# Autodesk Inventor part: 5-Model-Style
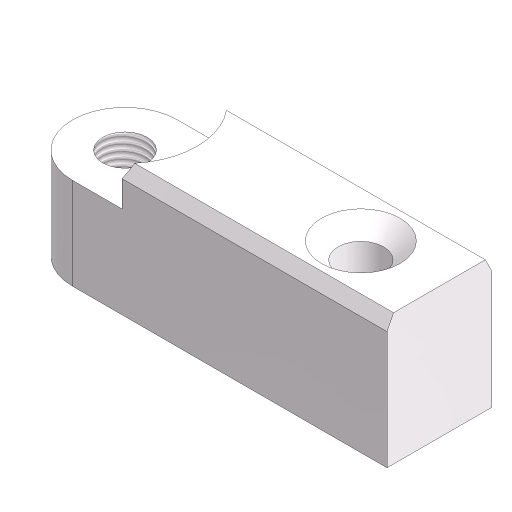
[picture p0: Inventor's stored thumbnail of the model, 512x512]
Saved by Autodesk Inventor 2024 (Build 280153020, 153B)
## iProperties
Company: ATC
Shininess: 21.0
Length Units: 11269
Angle Units: 11279
Time Units: 11290
Mass Units: 11283
Compacted: True
Created: 2023-03
Part Number: 5-Model-Style
Document SubType Name: Modeling
Designer: Andrzej Jaskulski
Material: Kurs-STD
Density: 1 g/cm^3
Appearance: Kurs-STD
Checked By: A.J.
Engr Approved By: Andrzej Jaskulski
Mfg Approved By: Andrzej Jaskulski
Authority: A.J.
Density: 0.0
Volumn: 0.0
Area: 0.0
PropertySet Name: Model Information
Control State: 0
Master: False
Checked Out: False
Title: A.J.: Kurs R2024-MEP
Author: Andrzej Jaskulski
Revision Number: 1/24
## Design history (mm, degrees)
sketch "Podstawa"
  geometry: L1 (0, 0)-(140, 0); L2 (140, 0)-(140, 40); L3 (140, 40)-(0, 40); L4 (0, 40)-(0, 0)
  constraints: 8 end point, 2 parallel, 1 horizontal, 1 perpendicular, 1 other
  dimensions: "L1" = 140 distance of L1.start L1.end; "L2" = 40 distance of L1.end L2.end
extrude "Baza" new body sketch "Podstawa" taper "d1" = 0 deg; distance "Ha" = 50
hole "Otwór W" diameter "d18" = 17; stored, may be unused: drill point angle "d10" = 118 deg, countersink angle "d22" = 90 deg; dims "d6" = 42, "d7" = 55, "d8" = 15, "d9" = 45, "d16" = 20, "d17" = 30
hole "Otwór St" diameter "d11" = 17.4; stored, may be unused: countersink angle "d13" = 90 deg, drill point angle "d51" = 118 deg; dims "d12" = 30, "d14" = 20 (= 0.5 x L2), "d46" = 6, "d48" = 2, "d50" = 8, "R1" = 30
node "Bryła1"
node "Korpusy bryłowe"
node "Korpusy powierzchniowe"
node "Początek"
fillet "Zaokrąglenie" dims "d3" = 20
chamfer "Faza" distance "d4" = 2.5; stored, may be unused: second distance "d5" = 5, angle "d15" = 45 deg
node "Płaszczyzna YZ"
node "Płaszczyzna XZ"
node "Płaszczyzna XY"
node "Oś X"
node "Oś Y"
node "Oś Z"
node "Punkt  środkowy"
other parameters: "d2" = 90 deg
